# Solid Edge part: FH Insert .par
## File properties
Author: Dan
Template: metric part.par
Last saved by: Dan
Revision: 54
Application: Solid Edge
Accuracy: 0.990
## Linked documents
TYRE HU 107X37.par
WHEEL TREAD[4].par
6203 Outer.asm
6203.asm
WHEEL CENTRE HUP125X36H45.par
WHEEL CENTRE[3].par
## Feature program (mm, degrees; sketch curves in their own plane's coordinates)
sketch for "RevolvedProtrusion_1" plane through (0, 0, -20.293) normal (0, 0, 1) x-axis (0, -1, 0)
revolve "RevolvedProtrusion_1" add full turn 360 deg about sketch line (-34.2947, 37.2947) -> (-34.2947, 31.2947)  Profile_Plane1_Distance = 2 mm
sketch for "RevolvedProtrusion_2" plane through (0, 0, -20.2931) normal (0, 0, 1) x-axis (0, -1, 0)
revolve "RevolvedProtrusion_2" add full turn 360 deg about sketch line (-20.5061, 23.5061) -> (-20.5061, 17.5061)  Profile_Plane1_Distance = 2 mm
sketch for "Hole_1" plane through (0, 0, -36) normal (0, 0, -1) x-axis (-1, 0, 0)
  hole centre (-34.2947, 34.2947) bore radius 0.55
hole "Hole_1" diameter 1.1 finite  TaperAngle = 3 deg
sketch for "unnamed Hole 1" plane through (0, 0, -36) normal (0, 0, -1) x-axis (-1, 0, 0)
  hole centre (-20.5061, 20.5061) bore radius 0.55
hole "unnamed Hole 1" finite
pattern "unnamed Pattern 1" of "Hole_1", "unnamed Hole 1"
pattern "unnamed Pattern 2" of "RevolvedProtrusion_1", "RevolvedProtrusion_2", "unnamed Pattern 1"
revolve "unnamed RevolvedProtrusion 1" add full turn 360 deg
revolve "unnamed RevolvedProtrusion 2" add full turn 360 deg
hole "unnamed Hole 2" finite
hole "unnamed Hole 3" finite
revolve "unnamed RevolvedProtrusion 3" add full turn 360 deg
revolve "unnamed RevolvedProtrusion 4" add full turn 360 deg
hole "unnamed Hole 4" finite
hole "unnamed Hole 5" finite
revolve "unnamed RevolvedProtrusion 5" add full turn 360 deg
revolve "unnamed RevolvedProtrusion 6" add full turn 360 deg
hole "unnamed Hole 6" finite
hole "unnamed Hole 7" finite
sketch for "unnamed RevolvedCutout 1" plane through (0, 0, 0) normal (1, 0, 0) x-axis (0, 1, 0)
  line (58, -20.093) -> (55.65, -20.093)
  line (55.65, -20.093) -> (55.65, -23.093)
  line (55.65, -23.093) -> (58, -23.093)
  line (58, -23.093) -> (58, -24.593)
  line (58, -24.593) -> (53, -24.593)
  line (53, -24.593) -> (53, -29.7)
  line (53, -29.7) -> (58, -29.7)
  line (58, -29.7) -> (58, -31.2)
  line (58, -31.2) -> (55.65, -31.2)
  line (55.65, -31.2) -> (55.65, -34.2)
  line (55.65, -34.2) -> (58, -34.2)
  dimension (linear) = 55.65
  dimension (linear) = 58
  dimension (linear) = 58
  dimension (linear) = 53
  dimension (linear) = 55.65
  dimension (linear) = 53
revolve "unnamed RevolvedCutout 1" cut full turn 360 deg
sketch for "unnamed Protrusion 1" plane through (0, 0, 0) normal (0, 0, 1) x-axis (1, 0, 0)
extrude "unnamed Protrusion 1" add finite 36 along -normal
boolean "unnamed Boolean 1"
boolean "unnamed Boolean 2"
sketch for "unnamed RevolvedCutout 2" plane through (0, 0, 0) normal (0, -1, 0) x-axis (1, 0, 0)
revolve "unnamed RevolvedCutout 2" cut full turn 360 deg
boolean "unnamed Boolean 3"
sketch for "unnamed RevolvedCutout 3" plane through (0, 0, 0) normal (0, -1, 0) x-axis (1, 0, 0)
revolve "unnamed RevolvedCutout 3" cut full turn 360 deg
boolean "unnamed Boolean 4"
sketch for "unnamed RevolvedProtrusion 7" plane through (0, 0, 0) normal (0, -1, 0) x-axis (1, 0, 0)
revolve "unnamed RevolvedProtrusion 7" add finite 360 deg about sketch line (0, 0) -> (0, -22.8845)
sketch for "unnamed RevolvedCutout 4" plane through (0, 0, 0) normal (0, -1, 0) x-axis (1, 0, 0)
revolve "unnamed RevolvedCutout 4" cut full turn 360 deg
Other named dimensions: "CopyConstruction_1": XScale = 1; YScale = 1; ZScale = 1 | "CoordinateSystem_2": Y_Rotation = 90 deg | "CopyConstruction_2": XScale = 1; YScale = 1; ZScale = 1 | "CopyConstruction_3": XScale = 1.015; YScale = 1.015; ZScale = 1.015 | "CopyConstruction_4": XScale = 1.015; YScale = 1.015; ZScale = 1.015 | "Face_Move_1": Distance = 6 mm | "CopyConstruction_5": XScale = 1; YScale = 1; ZScale = 1 | "CopyConstruction_6": XScale = 1.015; YScale = 1.015; ZScale = 1.015
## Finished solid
Body 1: sheet body, 1 face, 2 edges, 0 vertices.
  Faces by surface: cylinder 1
  Edges by curve: circle 2
Body 2: solid body, 8 faces, 8 edges, 0 vertices.
  Faces by surface: cylinder 3, torus 3, plane 2
  Edges by curve: circle 8
Body 3: solid body, 8 faces, 8 edges, 0 vertices.
  Faces by surface: torus 4, cylinder 2, plane 2
  Edges by curve: circle 8
Body 4: solid body, 64 faces, 131 edges, 71 vertices.
  Faces by surface: plane 28, cylinder 24, torus 5, cone 4, spun 2, spline 1
  Edges by curve: circle 92, line 33, curve on surface 4, spline 2
Body 5: solid body, 64 faces, 128 edges, 94 vertices.
  Faces by surface: plane 28, cylinder 24, torus 6, cone 4, spun 2
  Edges by curve: circle 94, line 32, ellipse 2
Body 6: solid body, 149 faces, 362 edges, 232 vertices, 7 separate solids.
  Faces by surface: plane 129, cylinder 11, spun 7, cone 2
  Edges by curve: line 332, circle 30
Body 7: solid body, 66 faces, 176 edges, 112 vertices.
  Faces by surface: cylinder 26, plane 21, cone 11, spun 6, torus 2
  Edges by curve: circle 88, line 32, spline 32, curve on surface 16, intersection 8
Body 8: solid body, 118 faces, 241 edges, 124 vertices.
  Faces by surface: plane 78, cylinder 18, cone 11, sphere 8, spun 2, torus 1
  Edges by curve: line 166, circle 71, intersection 4
Bounding box of the edges (mm; curved faces can reach further): 124.721 x 124.721 x 54.820, from (-62.3603, -62.3603, -36) to (62.3603, 62.3603, 18.8199).
Cylindrical faces by radius (mm): R5 x16, R5.075 x32, R8.5 x2, R16.45 x2, R18.8116 x1, R20 x2, R20.3 x2, R21.8198 x5, R24.4973 x1, R24.8648 x2, R26.8948 x5, R31.4973 x3, R31.9698 x4, R35.75 x3, R38.57 x6, R38.8542 x6, R40.75 x3, R45.5 x3, R46.1825 x2, R53 x1, R55.5 x1, R55.65 x2, R56.3325 x1, R58 x4
Conical faces (half-angle, radius in mm at the cone's reference point): 1 deg R18.2993 x2, 1 deg R18.3793 x1, 2 deg R17.0012 x3, 2 deg R18.9242 x2, 2 deg R19.3388 x3, 3 deg R0.55 x8, 75.0002 deg R50.5001 x1, 75.0002 deg R51.2574 x1, 75.0002 deg R51.2576 x1, 75.0007 deg R50.5 x1, 89.9983 deg R26.9973 x9
Toroidal faces (ring radius, tube radius in mm): R9.5 r1 x2, R14.275 r3.2802 x1, R19 r1 x4, R19.285 r1.015 x4, R20.0044 r1.015 x1, R20.4107 r1.015 x3, R30.4973 r1 x2, R30.9548 r1.015 x4
Spherical faces by radius (mm): R3 x8
Planar faces by outward normal: +x 38, +y 46, +z 68, -x 34, -y 38, -z 58, oblique 6
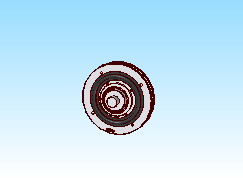
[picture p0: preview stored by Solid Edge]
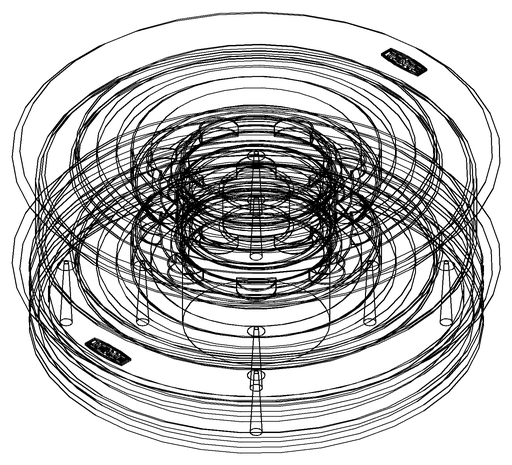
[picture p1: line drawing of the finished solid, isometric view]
